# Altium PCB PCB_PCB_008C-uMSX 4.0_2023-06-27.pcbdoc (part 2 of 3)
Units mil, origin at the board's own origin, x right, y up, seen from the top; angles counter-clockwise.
Board outline 14478.11 x 5217.07 mil, 2 copper layers (Top Layer, Bottom Layer); 184 components, 339 nets, 1501 pads, 946 vias.
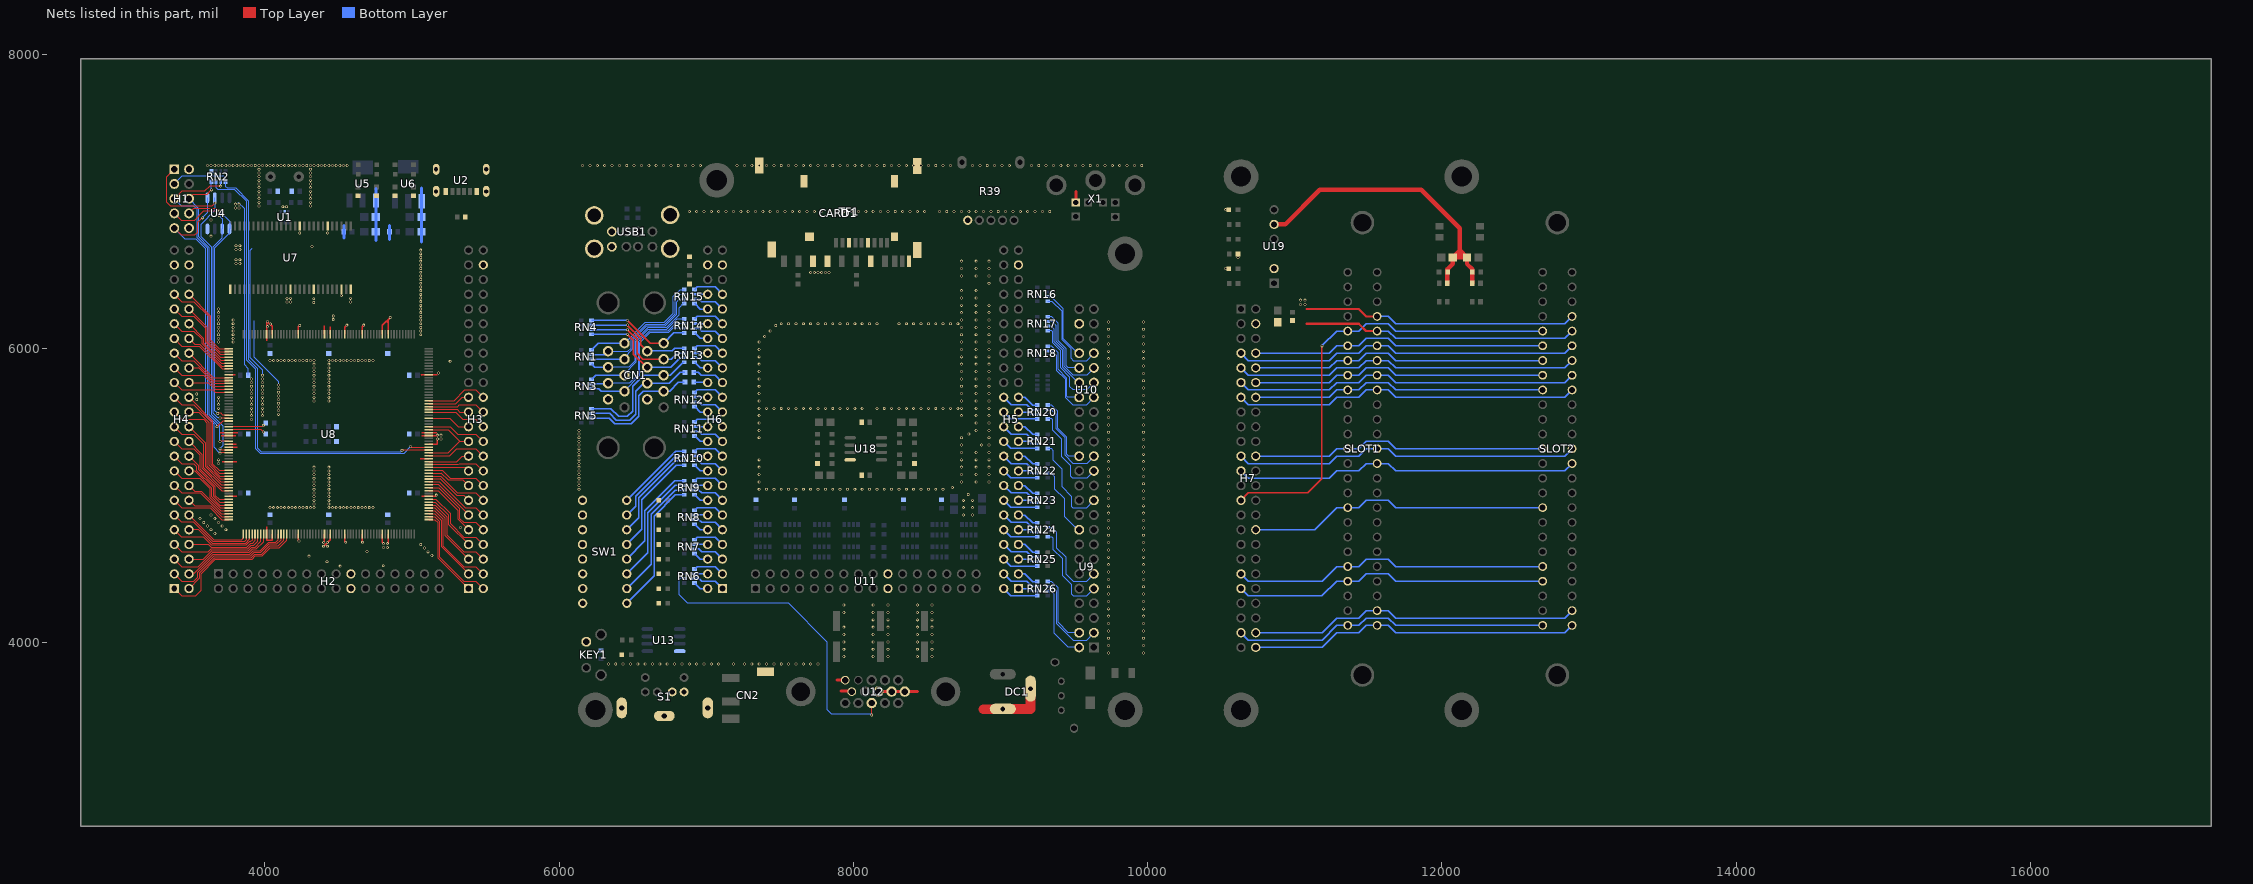
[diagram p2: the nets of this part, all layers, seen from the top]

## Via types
v1: diameter 20, hole 12, Top Layer to Bottom Layer, 944 vias
v2: diameter 24, hole 12, Top Layer to Bottom Layer, 2 vias

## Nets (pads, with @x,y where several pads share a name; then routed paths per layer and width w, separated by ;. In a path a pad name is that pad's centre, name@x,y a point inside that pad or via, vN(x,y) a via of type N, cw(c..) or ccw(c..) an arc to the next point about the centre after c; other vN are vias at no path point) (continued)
A12: H7.23 RN20.8 SLOT1.23 SLOT2.23 U10.1 | length 3008
  Bottom Layer w6: RN20.8@9320.43,5519.81 9347.24,5519.81 9354,5513.05 9354,5443.05 9415,5382.05 9415,5261.59 9476,5200.59 9476,5131.05 9490,5117.05 9585,5117.05 U10.1@9635,5167.05
  Bottom Layer w10: H7.23@10635,5167.05 10685,5117.05 11235,5117.05 11285,5167.05 11435,5167.05 11485.03,5217.08 SLOT1.23@11560,5217.08 11634.98,5217.08 11685.01,5167.05 12834.97,5167.05 SLOT2.23@12885,5217.08
A13: H7.22 RN20.5 SLOT1.26 SLOT2.26 U10.4 | length 2506.4
  Bottom Layer w6: RN20.5@9320.43,5614.29 9347.76,5614.29 9390,5572.05 9390,5457.96 9451,5396.96 9451,5279.08 9463.03,5267.05 U10.4@9535,5267.05
  Bottom Layer w10: H7.22@10735,5267.05 11235,5267.05 11285,5317.05 SLOT1.26@11359.97,5317.05 ; SLOT1.26@11360,5317.08 11435.02,5317.08 11484.99,5367.05 11635.01,5367.05 11684.98,5317.08 SLOT2.26@12685,5317.08
A14: H7.21 RN20.6 SLOT1.25 SLOT2.25 U10.3 | length 2966.7
  Bottom Layer w6: RN20.6@9320.43,5582.8 9345.91,5582.8 9378,5550.71 9378,5452.99 9439,5391.99 9439,5274.11 9496.06,5217.05 9585,5217.05 U10.3@9635,5267.05
  Bottom Layer w10: H7.21@10635,5267.05 10685,5217.05 11235,5217.05 11285,5267.05 11435,5267.05 11485.03,5317.08 SLOT1.25@11560,5317.08 11634.98,5317.08 11685.01,5267.05 12834.97,5267.05 SLOT2.25@12885,5317.08
A15: H7.32 RN22.7 SLOT1.18 SLOT2.18 U9.18 | length 2551.6
  Bottom Layer w6: RN22.7@9320.43,5151.3 9345.75,5151.3 9367,5130.05 9367,5047.02 9432,4982.02 9432,4859.9 9529.93,4761.97 U9.18@9535,4767.05
  Bottom Layer w10: H7.32@10735,4767.05 11136.97,4767.05 11287,4917.08 SLOT1.18@11360,4917.08 11435.03,4917.08 11485,4967.05 11635,4967.05 11684.97,4917.08 SLOT2.18@12685,4917.08
AS_CK: H1.1 U4.6 U8.36 | length 2462.8
  Top Layer w6: H1.1@3385,7217.05 3335,7167.05 3335,6992.05 3360,6967.05 3640,6967.05 v1@3655,6982.05 ; v1(3695,5317.05) 3703.27,5308.78 U8.36@3755.86,5308.78
  Bottom Layer w6: U4.6@3660,7022.66 v1(3660,6987.05) 3660,6937.05 3564,6841.05 3564,6761.99 3636,6689.99 3636,5553.02 3715,5474.02 3715,5337.05 v1(3695,5317.05)
AS_CS: H1.8 U4.1 U8.24 | length 1758.2
  Top Layer w6: H1.8@3485,6917.05 3515,6947.05 3675,6947.05 v1(3690,6932.05) ; v1(3680,5557.05) 3702.95,5557.05 3715,5545 U8.24@3755.86,5545
  Bottom Layer w6: v1(3680,5557.05) 3660,5577.05 3660,6685.08 3760,6785.08 U4.1@3760,6811.44 3760,6862.05 v1(3690,6932.05)
AS_DI: H1.7 U4.2 U8.25 | length 1862.8
  Top Layer w6: H1.7@3385,6917.05 3435,6867.05 3520,6867.05 3583,6930.05 3662,6930.05 v1(3690,6902.05) ; v1(3695,5527.05) 3696.73,5525.32 U8.25@3755.86,5525.32
  Bottom Layer w6: v1(3690,6902.05) 3710,6882.05 U4.2@3710,6811.44 3710,6752.05 3648,6690.05 3648,5557.99 3678.94,5527.05 v1(3695,5527.05)
AS_DO: H1.9 U4.5 U8.37 | length 2211.5
  Top Layer w6: H1.9@3385,6817.05 3435,6767.05 3520,6767.05 3540,6787.05 3540,6852.05 v1(3575,6887.05) ; v1(3695,5287.05) 3697.05,5289.1 U8.37@3755.86,5289.1
  Bottom Layer w6: H1.9@3385,6817.05 3460,6742.05 3533.03,6742.05 3600,6675.08 3600,5538.11 3655,5483.11 3655,5327.05 v1(3695,5287.05) ; v1(3575,6887.05) 3575,6887.66 3610,6922.66 U4.5@3610,7022.66
BDIR: H7.37 RN24.6 SLOT1.10 SLOT2.10 U9.11 | length 2814.1
  Bottom Layer w6: RN24.6@9320.43,4782.8 9349.25,4782.8 9380.03,4752.02 9380.03,4645.96 9444,4581.99 9444,4468.05 9495,4417.05 9585,4417.05 U9.11@9635,4467.05
  Bottom Layer w10: H7.37@10635,4467.05 10685,4417.05 11186.97,4417.05 11286.97,4517.05 11360,4517.05 11404.94,4517.05 ; SLOT1.10@11360,4517.08 11404.94,4517.08 11435.03,4517.08 11485,4567.05 11635,4567.05 11684.97,4517.08 SLOT2.10@12685,4517.08
C_CE: H1.6 RN2.4 U8.33 | length 2030.2
  Top Layer w6: H1.6@3485,7017.05 3515,7047.05 3607.5,7047.05 v1(3637.5,7077.05) ; v1(3695,5367.05) 3755.07,5367.05 U8.33@3755.86,5367.84
  Bottom Layer w6: H1.6@3485,7017.05 3552,6950.05 3552,6757.02 3624,6685.02 3624,5548.05 3695,5477.05 v1(3695,5367.05) ; v1(3637.5,7077.05) 3637.5,7131.35 RN2.4@3637.76,7131.61
C_CONF: H1.5 RN2.2 U8.26 | length 2195.7
  Top Layer w6: H1.5@3385,7017.05 3435,7067.05 3590,7067.05 3625,7102.05 v1(3700,7102.05) ; v1(3675,5467.05) 3713.58,5505.63 U8.26@3755.86,5505.63
  Bottom Layer w6: H1.5@3385,7017.05 3435,6967.05 3518.03,6967.05 3540,6945.08 3540,6752.05 3612,6680.05 3612,5543.08 3675,5480.08 v1(3675,5467.05) ; v1(3700,7102.05) 3700.75,7102.8 RN2.2@3700.75,7131.61
C_DONE: H1.3 RN2.1 U8.145 | length 3510.8
  Top Layer w6: v1(4932.5,5307.05) 4934.23,5308.78 U8.145@5114.14,5308.78
  Bottom Layer w6: H1.3@3385,7117.05 3436,7168.05 3721.55,7168.05 3732.24,7157.36 RN2.1@3732.24,7131.61 3732.24,7101.61 3743.8,7090.05 3802.29,7090.05 3888.5,7003.84 3888.5,5925.52 3950,5864.02 3950,5324.02 3976.97,5297.05 4922.5,5297.05 v1(4932.5,5307.05)
C_STAT: RN2.3 U8.146 | length 3201.4
  Top Layer w6: v1(4990,5332.05) 4993.58,5328.47 U8.146@5114.14,5328.47
  Bottom Layer w6: RN2.3@3669.25,7131.61 3669.25,7092.8 3684,7078.05 3797.32,7078.05 3876.5,6998.87 3876.5,5920.55 3938,5859.05 3938,5319.05 3972,5285.05 4943,5285.05 v1(4990,5332.05)
CLK21M: R9.2 U8.28 | length 238.6
  Top Layer w6: U8.28@3755.86,5466.26 3979.21,5466.26 v1(3990,5477.05)
CLOCK: H7.27 RN21.8 SLOT1.42 SLOT2.42 U9.21 | length 3750.4
  Top Layer w10: H7.27@10635,4967.05 10685,5017.05 11090,5017.05 11185,5112.05 v1(11185,6017.05)
  Bottom Layer w6: RN21.8@9320.43,5319.81 9344,5319.81 9355,5308.81 9355,5242.05 9415,5182.05 9415,5061.59 9482.03,4994.56 9482.03,4925.02 9490,4917.05 9585,4917.05 U9.21@9635,4967.05
  Bottom Layer w10: v1(11185,6017.05) 11285.02,6117.07 SLOT1.42@11360,6117.07 11435,6117.07 11484.98,6167.05 11635.02,6167.05 11685,6117.07 SLOT2.42@12685,6117.07
CS1: H7.48 RN26.7 SLOT1.1 SLOT2.1 U9.2 | length 2784.3
  Bottom Layer w6: RN26.7@9320.43,4351.3 9345.75,4351.3 9367,4330.05 9367,4062.02 9461.97,3967.05 U9.2@9535,3967.05
  Bottom Layer w10: H7.48@10735,3967.05 11186.97,3967.05 11286.97,4067.05 11434.99,4067.05 11485.02,4117.08 SLOT1.1@11560,4117.08 11634.97,4117.08 11685,4067.05 12834.97,4067.05 SLOT2.1@12885,4117.08
CS2: H7.45 RN26.6 SLOT1.2 SLOT2.2 U9.3 | length 2769.2
  Bottom Layer w6: RN26.6@9320.43,4382.8 9349.25,4382.8 9379,4353.05 9379,4133.05 9495,4017.05 9585,4017.05 U9.3@9635,4067.05
  Bottom Layer w10: H7.45@10635,4067.05 10685,4017.05 11186.97,4017.05 11287,4117.08 SLOT1.2@11360,4117.08 11435.02,4117.08 11484.99,4167.05 11635,4167.05 11684.97,4117.08 SLOT2.2@12685,4117.08
CS12: H7.46 RN26.5 SLOT1.3 SLOT2.3 U9.4 | length 2748.5
  Bottom Layer w6: RN26.5@9320.43,4414.29 9347.76,4414.29 9391,4371.05 9391,4138.02 9461.97,4067.05 U9.4@9535,4067.05
  Bottom Layer w10: H7.46@10735,4067.05 11186.97,4067.05 11286.97,4167.05 11435,4167.05 11485.03,4217.08 SLOT1.3@11560,4217.08 11634.97,4217.08 11685,4167.05 12834.97,4167.05 SLOT2.3@12885,4217.08
D0: H7.14 RN18.5 SLOT1.34 SLOT2.34 U10.12 | length 2509.9
  Bottom Layer w6: RN18.5@9320.43,6014.29 9347.76,6014.29 9391,5971.05 9391,5856.96 9451,5796.96 9451,5673.05 9457,5667.05 U10.12@9535,5667.05
  Bottom Layer w10: H7.14@10735,5667.05 11235,5667.05 11285,5717.05 11359.98,5717.05 11435.02,5717.07 11485,5767.05 11635,5767.05 11684.98,5717.07 SLOT2.34@12685,5717.07
D1: H7.13 RN18.6 SLOT1.33 SLOT2.33 U10.11 | length 2972.2
  Bottom Layer w6: RN18.6@9320.43,5982.8 9349.25,5982.8 9379,5953.05 9379,5851.99 9439,5791.99 9439,5667.99 9489.95,5617.05 9585,5617.05 U10.11@9635,5667.05
  Bottom Layer w10: H7.13@10635,5667.05 10685,5617.05 11235,5617.05 11285,5667.05 11435,5667.05 11485.02,5717.07 SLOT1.33@11560,5717.07 11634.98,5717.07 11685,5667.05 12834.98,5667.05 SLOT2.33@12885,5717.07
D2: H7.12 RN17.7 SLOT1.36 SLOT2.36 U10.14 | length 2504.8
  Bottom Layer w6: RN17.7@9320.43,6151.3 9345.75,6151.3 9367,6130.05 9367,6043.08 9422,5988.08 9422,5872.02 9526.97,5767.05 U10.14@9535,5767.05
  Bottom Layer w10: H7.12@10735,5767.05 11235,5767.05 11285,5817.05 11359.98,5817.05 11435.02,5817.07 11485,5867.05 11635,5867.05 11684.98,5817.07 SLOT2.36@12685,5817.07
D3: H7.11 RN17.8 SLOT1.35 SLOT2.35 U10.13 | length 3005.1
  Bottom Layer w6: RN17.8@9320.43,6119.81 9347.24,6119.81 9355,6112.05 9355,6037.05 9410,5982.05 9410,5867.05 9472,5805.05 9472,5740.05 9495,5717.05 9585,5717.05 U10.13@9635,5767.05
  Bottom Layer w10: H7.11@10635,5767.05 10685,5717.05 11235,5717.05 11285,5767.05 11435,5767.05 11485.02,5817.07 SLOT1.35@11560,5817.07 11634.98,5817.07 11685,5767.05 12834.98,5767.05 SLOT2.35@12885,5817.07
D4: H7.10 RN17.5 SLOT1.38 SLOT2.38 U10.16 | length 2507.6
  Bottom Layer w6: RN17.5@9320.43,6214.29 9347.76,6214.29 9391,6171.05 9391,6053.02 9446,5998.02 9446,5881.96 9460.91,5867.05 U10.16@9535,5867.05
  Bottom Layer w10: H7.10@10735,5867.05 11235,5867.05 11285.02,5917.07 SLOT1.38@11360,5917.07 11435.02,5917.07 11485,5967.05 11635,5967.05 11684.98,5917.07 SLOT2.38@12685,5917.07
D5: H7.9 RN17.6 SLOT1.37 SLOT2.37 U10.15 | length 2969.8
  Bottom Layer w6: RN17.6@9320.43,6182.8 9349.25,6182.8 9379,6153.05 9379,6048.05 9434,5993.05 9434,5876.99 9493.94,5817.05 9585,5817.05 U10.15@9635,5867.05
  Bottom Layer w10: H7.9@10635,5867.05 10685,5817.05 11235,5817.05 11285,5867.05 11435,5867.05 11485.02,5917.07 SLOT1.37@11560,5917.07 11634.98,5917.07 11685,5867.05 12834.98,5867.05 SLOT2.37@12885,5917.07
D6: H7.8 RN16.7 SLOT1.40 SLOT2.40 U10.18 | length 2504.7
  Bottom Layer w6: RN16.7@9320.43,6351.3 9345.23,6351.3 9427,6269.53 9427,6066.56 9526.51,5967.05 U10.18@9535,5967.05
  Bottom Layer w10: H7.8@10735,5967.05 11235,5967.05 11285.02,6017.07 SLOT1.40@11360,6017.07 11435.02,6017.07 11485,6067.05 11635,6067.05 11684.98,6017.07 SLOT2.40@12685,6017.07
D7: H7.7 RN16.8 SLOT1.39 SLOT2.39 U10.17 | length 3006.5
  Bottom Layer w6: RN16.8@9320.43,6319.81 9349.75,6319.81 9415,6254.56 9415,6061.59 9477,5999.59 9477,5935.05 9495,5917.05 9585,5917.05 U10.17@9635,5967.05
  Bottom Layer w10: H7.7@10635,5967.05 10685,5917.05 11235.02,5917.05 11285.02,5967.05 11435,5967.05 11485.02,6017.07 SLOT1.39@11560,6017.07 11634.98,6017.07 11685,5967.05 12834.98,5967.05 SLOT2.39@12885,6017.07
DIP0: RN10.8 SW1.16 | length 527.7
  Bottom Layer w10: SW1.16@6459.5,4966.95 6791.84,5299.29 RN10.8@6849.56,5299.29
DIP1: RN10.7 SW1.15 | length 595.6
  Bottom Layer w10: SW1.15@6459.5,4866.95 6520,4927.45 6520,4994.82 6792.98,5267.8 RN10.7@6849.56,5267.8
DIP2: RN10.6 SW1.14 | length 663.4
  Bottom Layer w10: SW1.14@6459.5,4766.95 6541,4848.45 6541,4983.19 6794.1,5236.3 RN10.6@6849.56,5236.3
DIP3: RN10.5 SW1.13 | length 731.3
  Bottom Layer w10: SW1.13@6459.5,4666.95 6562,4769.45 6562,4971.57 6795.24,5204.81 RN10.5@6849.56,5204.81
DIP4: RN9.8 SW1.12 | length 729.8
  Bottom Layer w10: SW1.12@6459.7,4567.45 6583,4690.75 6583,4894.94 6787.35,5099.29 RN9.8@6849.56,5099.29
DIP5: RN9.7 SW1.11 | length 797.6
  Bottom Layer w10: SW1.11@6460.5,4467.15 6604,4610.65 6604,4883.31 6788.49,5067.8 RN9.7@6849.56,5067.8
DIP6: RN9.6 SW1.10 | length 865.4
  Bottom Layer w10: SW1.10@6460.5,4367.15 6625,4531.65 6625,4871.68 6789.61,5036.3 RN9.6@6849.56,5036.3
DIP7: RN9.5 SW1.9 | length 933.3
  Bottom Layer w10: SW1.9@6460.5,4267.15 6646,4452.65 6646,4860.06 6790.75,5004.81 RN9.5@6849.56,5004.81
EXTCLK: R10.2 U8.29 | length 240.2
  Top Layer w6: U8.29@3755.86,5446.58 3975.47,5446.58 v1(3990,5432.05)
GND: 5V.1@10551.5,6541.65 +12V.1 C1.1 C2.1 C3.1 C4.1 C5.1 C6.1 C7.1 C8.1 C9.1 C10.1 C11.1 C12.1 C13.1 C14.1 C15.1 C16.1 C17.1 C18.1 C19.1 C20.1 C21.1 C22.2 C23.2 C24.2 C32.1 C33.2 C38.1 C39.1 C40.1 C41.2 C42.1 C43.1 CARD1.2 CARD1.3 CARD1.6 CARD1.11 CARD1.12 CARD1.13 CARD1.14 CARD1.15 CN1.9 CN1.18 CN2.1 DC1.2 DC1.3 H1.2 H1.10 H2.19 H2.20 H3.46 H4.45 H4.46 H5.45 H6.45 H6.46 H7.4 KEY1.1 LED5.1 LED6.1 LED7.1 LED8.1 LED9.1 LED10.1 LED11.1 LED12.1 LED13.1 R5.2 R6.2 R7.2 R8.2 R22.1 R23.1 R24.2 R25.2 R26.2 R27.2 R28.2 R32.2 R33.2 R39.1 R43.1 R45.1 R46.1 RN2.5 S1.2 S1.4 S1.7 S1.8 S1.9 SLOT1.41 SLOT1.43 SLOT2.41 SLOT2.43 SW1.1 SW1.2 SW1.3 SW1.4 SW1.5 SW1.6 SW1.7 SW1.8 TF1.3 TF1.6 TF1.10 TF1.11 TF1.12 TF1.13 U1.2 U2.7 U2.A12 U2.B12 U4.4 U5.1 U6.1 U7.6 U7.12 U7.28 U7.41 U7.46 U7.52 U7.54 U8.10 U8.30 U8.31 U8.34 U8.35 U8.40 U8.52 U8.69 U8.71 U8.80 U8.89 U8.91 U8.96 U8.102 U8.109 U8.111 U8.129 U8.142 U8.147 U8.150 U8.151 U8.171 U8.190 U8.192 U8.199 U8.205 U8.210 U8.212 U8.221 U8.230 U8.232 U10.22 U11.19 U11.20 U12.5 U12.6 U12.7 U12.8 U12.10 U13.4 U18.4 U19.2 U19.5 USB1.4 USB1.8 USB1.9 X1.3 | length 12989.5
  Top Layer w10: 3697.5,5427.05 3755.7,5427.05 U8.30@3755.86,5426.89 3815,5426.89 ; 3702.5,5407.05 3755.7,5407.05 U8.31@3755.86,5407.21 3802.5,5407.21 ; 3710,5229.55 3755.38,5229.55 U8.40@3755.86,5230.04 3809.51,5230.04 3810,5229.55 ; U8.52@3755.86,4993.82 3810,4993.82 ; U8.35@3755.86,5328.47 3812.5,5328.47 ; U8.34@3755.86,5348.15 3807.5,5348.15 ; U8.10@3755.86,5820.59 3800,5820.59 ; 4011.76,4787.05 U8.69@4011.76,4737.92 4011.76,4696.05 4051.14,4696.05 U8.71@4051.14,4737.92 ; 4011.78,6052.05 U8.232@4011.78,6096.18 4011.78,6176.32 v1(4017.5,6182.05) 4051.14,6148.4 U8.230@4051.14,6096.18 ; U8.80@4228.31,4737.92 4228.31,4693.74 v1(4232.5,4689.55) ; U8.221@4228.31,6096.18 4228.31,6145.35 v1(4237.5,6154.55) ; v1(4400,4654.55) v1(4425,4679.55) 4444.84,4699.38 U8.91@4444.84,4737.92 ; v1(4400,4679.55) 4405.47,4685.01 U8.89@4405.47,4737.92 ; U8.212@4405.48,6096.18 4405.48,6154.55 ; U8.210@4444.85,6096.18 4444.85,6147.05 ; U8.96@4543.27,4737.92 4543.27,4688.78 v1(4550,4682.05) ; U8.205@4543.27,6096.18 4543.27,6142.81 v1(4557.5,6157.05) ; U8.102@4661.38,4737.92 4661.38,4685.67 v1(4665,4682.05) ; U8.199@4661.38,6096.18 4661.38,6145.92 v1(4672.5,6157.05) ; U8.109@4799.16,4737.92 4799.16,4680.38 v1(4807.5,4672.05) ; U8.192@4799.16,6096.18 4799.16,6156.21 4822.22,6179.27 ; v1(4832.5,4672.05) 4838.53,4678.08 U8.111@4838.53,4737.92 ; U8.190@4838.53,6096.18 4838.53,6172.83 ; v1(4852.5,6209.55) 4838.53,6195.58 ; 5055,5249.73 U8.142@5114.14,5249.73 ; 5062.5,5817.05 5066.04,5820.59 U8.171@5114.14,5820.59 5172.5,5820.59 ; 5065,5407.05 5113.98,5407.05 U8.150@5114.14,5407.21 5170.16,5407.21 v1(5172.5,5409.55) ; 5067.5,4994.55 5113.4,4994.55 U8.129@5114.14,4993.82 5156.77,4993.82 v1(5165,5002.05) ; 5067.5,5427.05 5113.98,5427.05 U8.151@5114.14,5426.89 5170,5426.89 ; U8.147@5114.14,5348.15 5172.5,5348.15 v1(5172.5,5384.55) ; 4822.22,6179.27 4832.1,6179.27 4838.53,6172.83 ; 4822.22,6179.27 4838.53,6195.58 ; 4838.53,6172.83 4838.53,6195.58
  Top Layer w15: 11080,6167.05 11435,6167.05 11484.98,6117.07 SLOT1.41@11560,6117.07 ; 11080,6267.05 11435,6267.05 11484.98,6217.07 SLOT1.43@11560,6217.07
  Top Layer w20: 7887.5,3744.55 7943.8,3744.55 U12.5@7944.25,3745 ; 7915,3669.55 7986.83,3669.55 U12.10@7989.33,3667.05 ; U12.8@8169.65,3667.05 U12.7@8259.8,3667.05 U12.6@8349.96,3667.05 8435,3667.05 ; X1.3@9512.01,6991.05 9512.01,7067.05
  Top Layer w30: U19.5@10860,6842.05 10935,6842.05 11170,7077.05 11860,7077.05 12121.87,6815.18 12121.87,6665.81 ; C43.1@12037.55,6442.05 12037.56,6536.66 12074.37,6573.47 C41.2@12074.37,6617.05 ; C42.1@12207.45,6442.05 12207.44,6536.66 12170.63,6573.47 C40.1@12170.63,6617.05 ; C41.2@12074.37,6617.05 12121.87,6617.05 ; C41.2@12074.37,6617.05 12121.87,6664.55 ; 12121.87,6617.05 C40.1@12170.63,6617.05 ; 12121.87,6617.05 12121.87,6664.55 ; 12121.87,6664.55 12121.87,6665.81 ; 12121.87,6665.81 C40.1@12170.63,6617.05
  Top Layer w66.93: 8885,3547.05 9013.62,3547.05 DC1.2@9015.51,3548.94 9204.49,3548.94 DC1.3@9204.49,3686.73
  Bottom Layer w6: 3820,6989.55 3862.5,6947.05 3862.5,5887.05 3887.56,5861.99 C21.1@3887.55,5817.05 ; 3915,6679.55 3900.5,6665.05 3900.5,5934.58 3985,5850.08 v1(3985,5817.05) ; 3926.5,6186.05 3926.5,5942.52 4092.5,5776.52 v1@4092.5,5747.05
  Bottom Layer w10: SLOT1.41@11560,6117.07 11634.98,6117.07 11685,6067.05 12834.98,6067.05 SLOT2.41@12885,6117.07 ; SLOT1.43@11560,6217.07 11634.98,6217.07 11685,6167.05 12834.98,6167.05 SLOT2.43@12885,6217.07
  Bottom Layer w20: 4537.44,6749.55 C17.1@4537.45,6792.05 4537.44,6834.55 ; 4755.55,6732.05 U5.1@4755.55,7004.55 4755.55,7087.05 ; 4847.5,6739.55 4847.5,6792.05 4847.5,6834.55 ; 5065.55,6722.05 U6.1@5065.55,7000.12 5065.55,7089.55
  other v1: 6335,3854.55 6385,3854.55 6435,3854.55 6485,3854.55 6535,3854.55 6585,3854.55 6635,3854.55 6685,3854.55 6735,3854.55 6785,3854.55 6835,3854.55 6885,3854.55 6935,3854.55 6985,3854.55 7035,3854.55 7085,3854.55 7185,3854.55 7260,3854.55 7310,3854.55 7360,3854.55 7410,3854.55 7460,3854.55 7510,3854.55 7560,3854.55 7610,3854.55 7660,3854.55 7710,3854.55 7760,3854.55 7935,3904.55 8135,3904.55 8235,3904.55 8435,3904.55 8535,3904.55 9735,3929.55 9972.5,3929.55 7935,3954.55 8135,3954.55 8235,3954.55 8435,3954.55 8535,3954.55 9735,3979.55 9972.5,3979.55 7935,4004.55 8135,4004.55 8235,4004.55 8435,4004.55 8535,4004.55 9735,4029.55 9972.5,4029.55 7935,4054.55 8135,4054.55 8235,4054.55 8435,4054.55 8535,4054.55 9735,4079.55 9972.5,4079.55 7935,4104.55 8135,4104.55 8235,4104.55 8435,4104.55 8535,4104.55 9735,4129.55 9972.5,4129.55 8135,4154.55 8235,4154.55 8435,4154.55 8535,4154.55 9735,4179.55 9972.5,4179.55 7935,4204.55 8135,4204.55 8235,4204.55 8435,4204.55 8535,4204.55 9735,4229.55 9972.5,4229.55 7935,4254.55 8135,4254.55 8235,4254.55 8435,4254.55 8535,4254.55 9735,4279.55 9972.5,4279.55 9735,4329.55 9972.5,4329.55 9735,4379.55 9972.5,4379.55 9735,4429.55 9972.5,4429.55 9735,4479.55 9972.5,4479.55 4512.5,4519.55 4805,4522.05 9735,4529.55 9972.5,4529.55 4422.5,4549.55 9735,4579.55 9972.5,4579.55 4300,4587.05 5135,4592.05 5110,4617.05 4695,4619.55 9735,4629.55 9972.5,4629.55 5085,4642.05 4807.5,4647.05 4832.5,4647.05 4425,4654.55 5060,4667.05 9735,4679.55 9972.5,4679.55 9735,4729.55 9972.5,4729.55 3660,4742.05 3635,4767.05 3735,4767.05 9735,4779.55 9972.5,4779.55 5330,4782.05 3610,4792.05 3710,4792.05 3585,4817.05 3685,4817.05 9735,4829.55 9972.5,4829.55 3560,4842.05 3660,4842.05 3635,4867.05 8747.5,4867.05 8810,4867.05 9735,4879.55 9972.5,4879.55 4035,4917.05 4060,4917.05 4085,4917.05 4110,4917.05 4135,4917.05 4160,4917.05 4185,4917.05 4210,4917.05 4235,4917.05 4260,4917.05 4285,4917.05 4310,4917.05 4335,4917.05 4435,4917.05 4460,4917.05 4485,4917.05 4510,4917.05 4535,4917.05 4560,4917.05 4585,4917.05 4610,4917.05 4635,4917.05 4660,4917.05 4685,4917.05 4710,4917.05 4735,4917.05 8747.5,4917.05 8810,4917.05 9735,4929.55 9972.5,4929.55 4335,4942.05 4435,4942.05 4335,4967.05 4435,4967.05 8747.5,4967.05 8810,4967.05 9735,4979.55 9972.5,4979.55 4335,4992.05 4435,4992.05 8781,5006.05 4335,5017.05 4435,5017.05 9735,5029.55 9972.5,5029.55 4335,5042.05 4435,5042.05 6135,5042.05 7360,5042.05 7410,5042.05 7460,5042.05 7510,5042.05 7560,5042.05 7610,5042.05 7660,5042.05 7710,5042.05 7760,5042.05 7810,5042.05 7860,5042.05 7910,5042.05 7960,5042.05 8010,5042.05 8060,5042.05 8110,5042.05 8160,5042.05 8210,5042.05 8260,5042.05 8310,5042.05 8360,5042.05 8410,5042.05 8460,5042.05 8510,5042.05 8560,5042.05 8610,5042.05 8672.5,5054.55 4335,5067.05 4435,5067.05 6135,5067.05 9735,5079.55 9972.5,5079.55 4335,5092.05 4435,5092.05 6135,5092.05 7360,5092.05 8735,5092.05 8835,5092.05 8922.5,5092.05 4335,5117.05 4435,5117.05 6135,5117.05 9735,5129.55 9972.5,5129.55 4335,5142.05 4435,5142.05 6135,5142.05 7360,5142.05 8735,5142.05 8835,5142.05 8922.5,5142.05 4335,5167.05 4435,5167.05 6135,5167.05 9735,5179.55 9972.5,5179.55 4335,5192.05 4435,5192.05 6135,5192.05 7360,5192.05 8735,5192.05 8835,5192.05 8922.5,5192.05 3685,5217.05 6135,5217.05 9735,5229.55 9972.5,5229.55 3685,5242.05 6135,5242.05 7360,5242.05 8735,5242.05 8835,5242.05 8922.5,5242.05 6135,5267.05 9735,5279.55 9972.5,5279.55 6135,5292.05 8735,5292.05 8835,5292.05 8922.5,5292.05 6135,5317.05 9735,5329.55 9972.5,5329.55 6135,5342.05 8735,5342.05 8872.5,5342.05 8922.5,5342.05 6135,5367.05 9735,5379.55 9972.5,5379.55 5197.5,5384.55 6135,5392.05 7360,5392.05 8735,5392.05 8922.5,5392.05 5197.5,5409.55 6135,5417.05 8785,5417.05 9735,5429.55 9972.5,5429.55 6135,5442.05 7360,5442.05 8835,5442.05 8922.5,5442.05 9735,5479.55 9972.5,5479.55 7360,5492.05 8835,5492.05 8922.5,5492.05 3910,5517.05 9735,5529.55 9972.5,5529.55 3910,5542.05 3985,5542.05 7360,5542.05 8735,5542.05 8835,5542.05 8922.5,5542.05 4092.5,5551.52 3910,5567.05 3985,5567.05 4092.5,5576.52 9735,5579.55 9972.5,5579.55 3685,5592.05 3910,5592.05 3985,5592.05 7360,5592.05 7410,5592.05 7460,5592.05 7510,5592.05 7560,5592.05 7610,5592.05 7660,5592.05 7710,5592.05 7760,5592.05 7810,5592.05 7860,5592.05 7910,5592.05 7960,5592.05 8010,5592.05 8060,5592.05 8160,5592.05 8210,5592.05 8260,5592.05 8310,5592.05 8360,5592.05 8410,5592.05 8460,5592.05 8510,5592.05 8560,5592.05 8610,5592.05 8660,5592.05 8710,5592.05 8735,5592.05 8835,5592.05 8922.5,5592.05 4092.5,5601.52 3685,5617.05 3910,5617.05 3985,5617.05 4092.5,5626.52 9735,5629.55 9972.5,5629.55 3685,5642.05 3910,5642.05 3985,5642.05 4335,5642.05 4435,5642.05 7360,5642.05 8735,5642.05 8835,5642.05 8922.5,5642.05 3537.5,5652.29 4092.5,5651.52 3685,5667.05 3910,5667.05 3985,5667.05 4335,5667.05 4435,5667.05 4092.5,5676.52 9735,5679.55 9972.5,5679.55 3537.5,5689.55 3910,5692.05 3985,5692.05 4335,5692.05 4435,5692.05 7360,5692.05 8735,5692.05 8835,5692.05 8922.5,5692.05 4092.5,5701.52 3910,5717.05 3985,5717.05 4335,5717.05 4435,5717.05 4092.5,5726.52 9735,5729.55 9972.5,5729.55 3910,5742.05 3985,5742.05 4335,5742.05 4435,5742.05 7360,5742.05 8735,5742.05 8835,5742.05 8922.5,5742.05 4092.5,5751.52 3910,5767.05 3985,5767.05 4335,5767.05 4435,5767.05 9735,5779.55 9972.5,5779.55 3910,5792.05 3985,5792.05 4335,5792.05 4435,5792.05 7360,5792.05 8735,5792.05 8835,5792.05 8922.5,5792.05 4335,5817.05 4435,5817.05 9735,5829.55 9972.5,5829.55 5180,5832.05 4335,5842.05 4435,5842.05 7360,5842.05 8735,5842.05 8835,5842.05 8922.5,5842.05 4335,5867.05 4435,5867.05 9735,5879.55 9972.5,5879.55 4335,5892.05 4435,5892.05 7360,5892.05 8735,5892.05 8835,5892.05 8922.5,5892.05 5260,5912.05 4035,5917.05 4060,5917.05 4085,5917.05 4110,5917.05 4135,5917.05 4160,5917.05 4185,5917.05 4210,5917.05 4235,5917.05 4260,5917.05 4285,5917.05 4310,5917.05 4335,5917.05 4435,5917.05 4460,5917.05 4485,5917.05 4510,5917.05 4535,5917.05 4560,5917.05 4585,5917.05 4610,5917.05 4635,5917.05 4660,5917.05 4685,5917.05 4710,5917.05 4735,5917.05 9735,5929.55 9972.5,5929.55 7360,5942.05 8735,5942.05 8835,5942.05 8922.5,5942.05 9735,5979.55 9972.5,5979.55 7360,5992.05 8735,5992.05 8835,5992.05 8922.5,5992.05 9735,6029.55 9972.5,6029.55 3685,6042.05 3785,6042.05 7360,6042.05 8735,6042.05 8835,6042.05 8922.5,6042.05 3685,6067.05 3785,6067.05 7397.5,6079.55 9735,6079.55 9972.5,6079.55 3685,6092.05 3785,6092.05 5060,6092.05 8735,6092.05 8835,6092.05 8922.5,6092.05 3685,6117.05 3785,6117.05 5060,6117.05 7435,6117.05 9735,6129.55 9972.5,6129.55 3685,6142.05 3785,6142.05 5060,6142.05 8735,6142.05 8835,6142.05 8922.5,6142.05 4017.5,6147.05 7472.5,6154.55 4037.5,6164.55 3685,6167.05 3785,6167.05 5060,6167.05 7510,6167.05 7560,6167.05 7610,6167.05 7660,6167.05 7710,6167.05 7760,6167.05 7810,6167.05 7860,6167.05 7910,6167.05 7960,6167.05 8010,6167.05 8060,6167.05 8110,6167.05 8160,6167.05 8310,6167.05 8360,6167.05 8410,6167.05 8460,6167.05 8510,6167.05 8560,6167.05 8610,6167.05 8660,6167.05 8710,6167.05 9735,6179.55 9972.5,6179.55 3685,6192.05 3785,6192.05 5060,6192.05 8735,6192.05 8835,6192.05 8922.5,6192.05 4465,6194.55 3685,6217.05 5060,6217.05 4465,6219.55 3685,6242.05 5060,6242.05 8735,6242.05 8835,6242.05 8922.5,6242.05 3685,6267.05 5060,6267.05 5060,6292.05 8735,6292.05 8835,6292.05 8922.5,6292.05 11040,6297.05 11070,6297.05 4332.5,6312.05 4150,6314.55 4175,6314.55 4582.5,6314.55 5060,6317.05 11040,6327.05 11070,6327.05 4332.5,6337.05 4150,6339.55 4175,6339.55 4582.5,6339.55 5060,6342.05 8735,6342.05 8835,6342.05 4520,6359.55 5060,6367.05 5060,6392.05 8735,6392.05 8835,6392.05 5060,6417.05 5060,6442.05 8922.5,6442.05 5060,6467.05 5060,6492.05 8735,6492.05 8835,6492.05 8922.5,6492.05 7710,6514.55 7735,6514.55 7760,6514.55 7785,6514.55 7810,6514.55 7835,6514.55 5060,6517.05 5060,6542.05 8735,6542.05 8835,6542.05 8922.5,6542.05 10530,6542.05 5060,6567.05 3805,6577.05 3830,6577.05 5060,6592.05 8735,6592.05 8835,6592.05 8922.5,6592.05 3805,6602.05 3830,6602.05 5060,6617.05 10615,6617.05 5060,6642.05 5060,6667.05 3805,6672.05 3830,6672.05 4320,6692.05 3805,6697.05 3830,6697.05 3635,6762.05 4237.5,6784.55 4427.5,6784.55 3635,6872.05 6885,6929.55 6935,6929.55 6985,6929.55 7035,6929.55 7085,6929.55 7135,6929.55 7185,6929.55 7235,6929.55 7285,6929.55 7335,6929.55 7385,6929.55 7435,6929.55 7485,6929.55 7535,6929.55 7585,6929.55 7635,6929.55 7685,6929.55 7735,6929.55 7785,6929.55 7835,6929.55 7885,6929.55 7935,6929.55 7985,6929.55 8035,6929.55 8085,6929.55 8135,6929.55 8185,6929.55 8235,6929.55 8285,6929.55 8335,6929.55 8385,6929.55 8435,6929.55 8485,6929.55 8585,6929.55 8635,6929.55 8685,6929.55 8735,6929.55 8785,6929.55 8835,6929.55 8885,6929.55 8935,6929.55 8985,6929.55 9035,6929.55 9085,6929.55 9135,6929.55 9185,6929.55 9235,6929.55 9285,6929.55 9335,6929.55 10530,6942.05 3800,6954.55 3825,6954.55 4122.5,6962.05 4147.5,6962.05 3960,6967.05 4310,6967.05 3800,6979.55 3825,6979.55 3960,6992.05 4310,6992.05 3960,7017.05 4310,7017.05 3960,7042.05 4310,7042.05 3960,7067.05 4310,7067.05 3960,7092.05 4310,7092.05 3960,7117.05 4310,7117.05 3960,7142.05 4310,7142.05 3960,7167.05 4310,7167.05 3960,7192.05 4310,7192.05 3960,7217.05 4310,7217.05 3610,7242.05 3635,7242.05 3660,7242.05 3685,7242.05 3710,7242.05 3735,7242.05 3760,7242.05 3785,7242.05 3810,7242.05 3835,7242.05 3860,7242.05 3885,7242.05 3910,7242.05 3935,7242.05 3960,7242.05 3985,7242.05 4010,7242.05 4035,7242.05 4060,7242.05 4085,7242.05 4110,7242.05 4135,7242.05 4160,7242.05 4185,7242.05 4210,7242.05 4235,7242.05 4260,7242.05 4285,7242.05 4310,7242.05 4335,7242.05 4360,7242.05 4385,7242.05 4410,7242.05 4435,7242.05 4460,7242.05 4485,7242.05 4510,7242.05 4535,7242.05 4560,7242.05 6160,7242.05 6210,7242.05 6260,7242.05 6310,7242.05 6360,7242.05 6410,7242.05 6460,7242.05 6510,7242.05 6560,7242.05 6610,7242.05 6660,7242.05 6710,7242.05 6760,7242.05 6810,7242.05 6860,7242.05 6910,7242.05 6960,7242.05 7210,7242.05 7260,7242.05 7310,7242.05 7360,7242.05 7410,7242.05 7460,7242.05 7510,7242.05 7560,7242.05 7610,7242.05 7660,7242.05 7710,7242.05 7760,7242.05 7810,7242.05 7860,7242.05 7910,7242.05 7960,7242.05 8010,7242.05 8060,7242.05 8110,7242.05 8160,7242.05 8210,7242.05 8260,7242.05 8310,7242.05 8360,7242.05 8410,7242.05 8460,7242.05 8510,7242.05 8560,7242.05 8610,7242.05 8660,7242.05 8810,7242.05 8860,7242.05 8910,7242.05 8960,7242.05 9010,7242.05 9060,7242.05 9210,7242.05 9260,7242.05 9310,7242.05 9360,7242.05 9410,7242.05 9460,7242.05 9510,7242.05 9560,7242.05 9610,7242.05 9660,7242.05 9710,7242.05 9760,7242.05 9810,7242.05 9860,7242.05 9910,7242.05 9960,7242.05
HSYNC: RN6.6 U12.13 | length 2140.6
  Top Layer w6: U12.13@8124.57,3589.1 8125,3588.67 v1(8125,3507.05)
  Bottom Layer w6: RN6.6@6849.56,4436.3 6824.25,4436.3 6814,4426.05 6814,4326.99 6870.94,4270.05 7555.94,4270.05 7819,4006.99 7819,3548.05 7850,3517.05 8115,3517.05 v1(8125,3507.05)
INT: H7.39 RN24.8 SLOT1.8 SLOT2.8 U9.9 | length 2849.9
  Bottom Layer w6: RN24.8@9320.43,4719.81 9347.24,4719.81 9356.03,4711.02 9356.03,4636.02 9420,4572.05 9420,4456.59 9481,4395.59 9481,4331.05 9495,4317.05 9585,4317.05 U9.9@9635,4367.05
  Bottom Layer w10: H7.39@10635,4367.05 10685,4317.05 11185,4317.05 11285,4417.05 11360,4417.05 11404.94,4417.05 ; SLOT1.8@11360,4417.08 11404.94,4417.08 11435.03,4417.08 11485,4467.05 11635,4467.05 11684.97,4417.08 SLOT2.8@12685,4417.08
IO0: CN1.1 RN1.5 RN15.8 | length 865.3
  Bottom Layer w6: CN1.1@6444.84,6035.16 6586.73,6177.05 6713.18,6177.05 6775.92,6239.79 6775.92,6352.97 6822.24,6399.29 RN15.8@6849.56,6399.29
  Bottom Layer w10: RN1.5@6220.44,5989.29 6266.31,6035.16 CN1.1@6444.84,6035.16
IO1: CN1.6 RN1.6 RN15.7 | length 893.4
  Bottom Layer w6: CN1.6@6333.03,5980.63 6468.32,5980.63 6489.74,6002.05 6489.74,6063.08 6591.7,6165.05 6718.15,6165.05 6787.92,6234.82 6787.92,6334.97 6820.75,6367.8 RN15.7@6849.56,6367.8
  Bottom Layer w10: RN1.6@6220.44,5957.8 6310.2,5957.8 CN1.6@6333.03,5980.63
IO2: CN1.2 RN1.7 RN15.6 | length 894.8
  Bottom Layer w6: CN1.2@6444.85,5926.1 6444.84,5940.18 6501.74,5997.08 6501.74,6058.11 6596.67,6153.05 6723.12,6153.05 6799.92,6229.85 6799.92,6316.97 6820,6337.05 6848.81,6337.05 RN15.6@6849.56,6336.3
  Bottom Layer w10: RN1.7@6220.44,5926.3 6444.64,5926.3 CN1.2@6444.85,5926.1
IO3: CN1.7 RN1.8 RN15.5 | length 928
  Bottom Layer w6: CN1.7@6333.03,5871.58 6472.4,5871.58 6513.74,5912.92 6513.74,6053.14 6601.64,6141.05 6728.09,6141.05 6811.92,6224.88 6811.92,6272.16 6844.56,6304.81 RN15.5@6849.56,6304.81
  Bottom Layer w10: RN1.8@6220.44,5894.81 6243.66,5871.58 CN1.7@6333.03,5871.58
IO4: CN1.3 RN3.5 RN14.8 | length 887
  Bottom Layer w6: CN1.3@6444.84,5817.05 6444.84,5827.05 6525.74,5907.94 6525.74,6048.17 6606.62,6129.05 6733.06,6129.05 6803.3,6199.29 RN14.8@6849.56,6199.29
  Bottom Layer w10: RN3.5@6220.44,5789.29 6248.19,5817.05 CN1.3@6444.84,5817.05
IO5: CN1.8 RN3.6 RN14.7 | length 928
  Bottom Layer w6: CN1.8@6333.03,5762.52 6477.4,5762.52 6537.74,5822.86 6537.74,6043.2 6611.59,6117.05 6738.03,6117.05 6788.78,6167.8 RN14.7@6849.56,6167.8
  Bottom Layer w10: RN3.6@6220.44,5757.8 6328.31,5757.8 CN1.8@6333.03,5762.52
IO6: CN1.4 RN3.7 RN14.6 | length 946.1
  Bottom Layer w6: CN1.4@6444.85,5707.99 6444.84,5712.99 6549.74,5817.89 6549.74,6038.23 6616.56,6105.05 6743,6105.05 6774.25,6136.3 RN14.6@6849.56,6136.3
  Bottom Layer w10: RN3.7@6220.44,5726.3 6270,5726.3 6288.31,5707.99 CN1.4@6444.85,5707.99
IO7: CN1.10 RN4.1 RN14.5 | length 721.8
  Top Layer w10: v1(6465,6189.29) 6619.13,6035.16 CN1.10@6710.98,6035.16
  Bottom Layer w10: RN4.1@6220.44,6189.29 v1(6465,6189.29) ; CN1.10@6710.98,6035.16 6780.63,6104.81 RN14.5@6849.56,6104.81
IO8: CN1.15 RN4.2 RN13.8 | length 735.4
  Top Layer w10: v1(6465,6157.8) 6554.17,6068.63 6554.17,6025.63 CN1.15@6599.17,5980.63
  Bottom Layer w10: RN4.2@6220.44,6157.8 v1(6465,6157.8) ; CN1.15@6599.17,5980.63 6600.59,5982.05 6770,5982.05 6787.24,5999.29 RN13.8@6849.56,5999.29
IO9: CN1.11 RN4.3 RN13.7 | length 784.5
  Top Layer w10: v1(6465,6126.3) 6530,6061.3 6530,5967.05 6570,5927.05 6710.03,5927.05 CN1.11@6710.99,5926.1
  Bottom Layer w10: RN4.3@6220.44,6126.3 v1(6465,6126.3) ; CN1.11@6710.99,5926.1 6760.98,5926.1 6802.68,5967.8 RN13.7@6849.56,5967.8
IO10: CN1.16 RN4.4 RN13.6 | length 803.5
  Top Layer w10: v1(6465,6094.81) 6505,6054.81 6505,5960.75 6594.17,5871.58 CN1.16@6599.17,5871.58
  Bottom Layer w10: RN4.4@6220.44,6094.81 v1(6465,6094.81) ; CN1.16@6599.17,5871.58 6599.64,5872.05 6760,5872.05 6824.25,5936.3 RN13.6@6849.56,5936.3
IO11: CN1.12 RN5.1 RN13.5 | length 902.7
  Bottom Layer w10: RN5.1@6220.44,5589.29 6352.76,5589.29 6405,5537.05 6465,5537.05 6500,5572.05 6500,5742.05 6575,5817.05 CN1.12@6710.98,5817.05 6756.81,5817.05 6844.56,5904.81 RN13.5@6849.56,5904.81
IO12: CN1.17 R2.1 RN5.2 | length 880.4
  Bottom Layer w10: RN5.2@6220.44,5557.8 6344.25,5557.8 6390,5512.05 6480,5512.05 6520,5552.05 6520,5708.35 6574.17,5762.52 CN1.17@6599.17,5762.52 6599.64,5762.05 6750,5762.05 6825,5837.05 R2.1@6855.34,5837.05
IO13: CN1.13 R1.1 RN5.3 | length 843.7
  Bottom Layer w10: RN5.3@6220.44,5526.3 6340.75,5526.3 6380,5487.05 6490,5487.05 6540,5537.05 6540,5677.05 6570.94,5707.99 CN1.13@6710.99,5707.99 6750.98,5707.99 6810.79,5767.8 R1.1@6849.56,5767.8
IO/1: H4.42 H6.41 RN15.1 U8.1 | length 737.6
  Top Layer w6: H4.42@3485,6367.05 3630.07,6221.98 3630.07,6057.89 3690.2,5997.76 U8.1@3755.86,5997.76
  Bottom Layer w10: RN15.1@6920.44,6399.29 6938.19,6417.05 7060,6417.05 H6.41@7110,6367.05
IO/2: H4.41 H6.42 RN15.2 U8.2 | length 718
  Top Layer w6: H4.41@3385,6367.05 3435,6317.05 3518.03,6317.05 3618.07,6217.01 3618.07,6052.92 3692.92,5978.07 U8.2@3755.86,5978.07
  Bottom Layer w10: RN15.2@6920.44,6367.8 7009.25,6367.8 H6.42@7010,6367.05
IO/3: H4.40 H6.39 RN15.3 U8.3 | length 674.4
  Top Layer w6: H4.40@3485,6267.05 3606.07,6145.98 3606.07,6047.95 3695.63,5958.39 U8.3@3755.86,5958.39
  Bottom Layer w10: RN15.3@6920.44,6336.3 6950.75,6336.3 6970,6317.05 7060,6317.05 H6.39@7110,6267.05
IO/4: H4.39 H6.40 RN15.4 U8.4 | length 669.5
  Top Layer w6: H4.39@3385,6267.05 3435,6217.05 3518.03,6217.05 3594.07,6141.01 3594.07,6042.98 3698.35,5938.7 U8.4@3755.86,5938.7
  Bottom Layer w10: RN15.4@6920.44,6304.81 6958.19,6267.05 H6.40@7010,6267.05
IO/5: H4.38 H6.37 RN14.1 U8.5 | length 610
  Top Layer w6: H4.38@3485,6167.05 3582.07,6069.98 3582.07,6038.01 3701.06,5919.02 U8.5@3755.86,5919.02
  Bottom Layer w10: RN14.1@6920.44,6199.29 6938.19,6217.05 7060,6217.05 H6.37@7110,6167.05
IO/6: H4.37 H6.38 RN14.2 U8.6 | length 590.4
  Top Layer w6: H4.37@3385,6167.05 3435,6117.05 3518.03,6117.05 3570.07,6065.01 3570.07,6033.03 3703.78,5899.33 U8.6@3755.86,5899.33
  Bottom Layer w10: RN14.2@6920.44,6167.8 7009.25,6167.8 H6.38@7010,6167.05
IO/7: H4.36 H6.35 RN14.3 U8.7 | length 566.7
  Top Layer w6: H4.36@3485,6067.05 3525.02,6027.02 3559.11,6027.02 3706.49,5879.65 U8.7@3755.86,5879.65
  Bottom Layer w10: RN14.3@6920.44,6136.3 6950.75,6136.3 6970,6117.05 7060,6117.05 H6.35@7110,6067.05
IO/8: H4.35 H6.36 RN14.4 U8.8 | length 561.9
  Top Layer w6: H4.35@3385,6067.05 3437.02,6015.02 3554.14,6015.02 3709.21,5859.96 U8.8@3755.86,5859.96
  Bottom Layer w10: RN14.4@6920.44,6104.81 6958.19,6067.05 H6.36@7010,6067.05
IO/11: H4.34 H6.33 RN13.1 U8.11 | length 557.3
  Top Layer w6: H4.34@3485,5967.05 3651.14,5800.91 U8.11@3755.86,5800.91
  Bottom Layer w10: RN13.1@6920.44,5999.29 6938.19,6017.05 7060,6017.05 H6.33@7110,5967.05
IO/12: H4.33 H6.34 RN13.2 U8.12 | length 537.7
  Top Layer w6: H4.33@3385,5967.05 3435,5917.05 3518.03,5917.05 3653.86,5781.22 U8.12@3755.86,5781.22
  Bottom Layer w10: RN13.2@6920.44,5967.8 7009.25,5967.8 H6.34@7010,5967.05
IO/13: H4.32 H6.31 RN13.3 U8.13 | length 532.8
  Top Layer w6: H4.32@3485,5867.05 3551.06,5867.05 3656.57,5761.54 U8.13@3755.86,5761.54
  Bottom Layer w10: RN13.3@6920.44,5936.3 6950.75,5936.3 6970,5917.05 7060,5917.05 H6.31@7110,5867.05
IO/14: H4.31 H6.32 RN13.4 U8.14 | length 527.9
  Top Layer w6: H4.31@3385,5867.05 3435,5817.05 3584.09,5817.05 3659.29,5741.85 U8.14@3755.86,5741.85
  Bottom Layer w10: RN13.4@6920.44,5904.81 6958.19,5867.05 H6.32@7010,5867.05
IO/15: H4.30 H6.29 R2.2 U8.15 | length 513.8
  Top Layer w6: H4.30@3485,5767.05 3617.12,5767.05 3662,5722.17 U8.15@3755.86,5722.17
  Bottom Layer w10: R2.2@6914.66,5837.05 6944.66,5837.05 6964.66,5817.05 7060,5817.05 H6.29@7110,5767.05
IO/16: H4.29 H6.30 R1.2 U8.16 | length 487.5
  Top Layer w6: H4.29@3385,5767.05 3435,5717.05 3650.15,5717.05 3664.72,5702.48 U8.16@3755.86,5702.48
  Bottom Layer w10: R1.2@6920.44,5767.8 7009.25,5767.8 H6.30@7010,5767.05
IO/43: H4.28 H6.27 RN12.1 U8.43 | length 865.1
  Top Layer w6: H4.28@3485,5667.05 3643,5509.05 3643,5216.93 3688.94,5170.99 U8.43@3755.86,5170.99
  Bottom Layer w10: RN12.1@6920.44,5699.29 6938.19,5717.05 7060,5717.05 H6.27@7110,5667.05
IO/44: H4.27 H6.28 RN12.2 U8.44 | length 845.5
  Top Layer w6: H4.27@3385,5667.05 3435,5617.05 3518.03,5617.05 3631,5504.08 3631,5211.96 3691.66,5151.3 U8.44@3755.86,5151.3
  Bottom Layer w10: RN12.2@6920.44,5667.8 7009.25,5667.8 H6.28@7010,5667.05
IO/45: H4.26 H6.25 RN12.3 U8.45 | length 840.6
  Top Layer w6: H4.26@3485,5567.05 3551.06,5567.05 3619,5499.11 3619,5206.99 3694.37,5131.62 U8.45@3755.86,5131.62
  Bottom Layer w10: RN12.3@6920.44,5636.3 6950.75,5636.3 6970,5617.05 7060,5617.05 H6.25@7110,5567.05
IO/46: H4.25 H6.26 RN12.4 U8.46 | length 835.7
  Top Layer w6: H4.25@3385,5567.05 3435,5517.05 3584.09,5517.05 3607,5494.14 3607,5202.02 3697.09,5111.93 U8.46@3755.86,5111.93
  Bottom Layer w10: RN12.4@6920.44,5604.81 6958.19,5567.05 H6.26@7010,5567.05
IO/47: H4.24 H6.23 RN11.1 U8.47 | length 737.5
  Top Layer w6: H4.24@3485,5467.05 3595,5357.05 3595,5197.05 3699.8,5092.25 U8.47@3755.86,5092.25
  Bottom Layer w10: RN11.1@6920.44,5499.29 6938.19,5517.05 7060,5517.05 H6.23@7110,5467.05
IO/48: H4.23 H6.24 RN11.2 U8.48 | length 717.9
  Top Layer w6: H4.23@3385,5467.05 3435,5417.05 3518.03,5417.05 3583,5352.08 3583,5192.08 3702.52,5072.56 U8.48@3755.86,5072.56
  Bottom Layer w10: RN11.2@6920.44,5467.8 7009.25,5467.8 H6.24@7010,5467.05
IO/49: H4.22 H6.21 RN11.3 U8.49 | length 674.3
  Top Layer w6: H4.22@3485,5367.05 3571,5281.05 3571,5187.11 3705.23,5052.88 U8.49@3755.86,5052.88
  Bottom Layer w10: RN11.3@6920.44,5436.3 6950.75,5436.3 6970,5417.05 7060,5417.05 H6.21@7110,5367.05
IO/50: H4.21 H6.22 RN11.4 U8.50 | length 669.4
  Top Layer w6: H4.21@3385,5367.05 3435,5317.05 3518.03,5317.05 3559,5276.08 3559,5182.14 3707.95,5033.19 U8.50@3755.86,5033.19
  Bottom Layer w10: RN11.4@6920.44,5404.81 6958.19,5367.05 H6.22@7010,5367.05
IO/53: H4.20 H6.19 RN10.1 U8.53 | length 661.4
  Top Layer w6: H4.20@3485,5267.05 3547,5205.05 3547,5177.17 3661,5063.17 3661,5003.02 3689.88,4974.14 U8.53@3755.86,4974.14
  Bottom Layer w10: RN10.1@6920.44,5299.29 6938.19,5317.05 7060,5317.05 H6.19@7110,5267.05
IO/54: H4.19 H6.20 RN10.2 U8.54 | length 641.8
  Top Layer w6: H4.19@3385,5267.05 3435,5217.05 3518.03,5217.05 3535,5200.08 3535,5172.2 3649,5058.2 3649,4998.05 3692.6,4954.45 U8.54@3755.86,4954.45
  Bottom Layer w10: RN10.2@6920.44,5267.8 7009.25,5267.8 H6.20@7010,5267.05
IO/55: H4.18 H6.17 RN10.3 U8.55 | length 620.6
  Top Layer w6: H4.18@3485,5167.05 3523.18,5167.05 3637,5053.22 3637,4993.08 3695.31,4934.77 U8.55@3755.86,4934.77
  Bottom Layer w10: RN10.3@6920.44,5236.3 6950.75,5236.3 6970,5217.05 7060,5217.05 H6.17@7110,5167.05
IO/56: H4.17 H6.18 RN10.4 U8.56 | length 615.7
  Top Layer w6: H4.17@3385,5167.05 3435,5117.05 3556.21,5117.05 3625,5048.25 3625,4988.11 3698.03,4915.08 U8.56@3755.86,4915.08
  Bottom Layer w10: RN10.4@6920.44,5204.81 6958.19,5167.05 H6.18@7010,5167.05
IO/57: H4.16 H6.15 RN9.1 U8.57 | length 559.6
  Top Layer w6: H4.16@3485,5067.05 3523,5029.05 3567.09,5029.05 3700.74,4895.4 U8.57@3755.86,4895.4
  Bottom Layer w10: RN9.1@6920.44,5099.29 6938.19,5117.05 7060,5117.05 H6.15@7110,5067.05
IO/58: H4.15 H6.16 RN9.2 U8.58 | length 540
  Top Layer w6: H4.15@3385,5067.05 3435,5017.05 3562.12,5017.05 3703.46,4875.71 U8.58@3755.86,4875.71
  Bottom Layer w10: RN9.2@6920.44,5067.8 7009.25,5067.8 H6.16@7010,5067.05
IO/59: H4.14 H6.13 RN9.3 U8.59 | length 535.1
  Top Layer w6: H4.14@3485,4967.05 3523,4929.05 3633.15,4929.05 3706.17,4856.03 U8.59@3755.86,4856.03
  Bottom Layer w10: RN9.3@6920.44,5036.3 6950.75,5036.3 6970,5017.05 7060,5017.05 H6.13@7110,4967.05
IO/60: H4.13 H6.14 RN9.4 U8.60 | length 530.2
  Top Layer w6: H4.13@3385,4967.05 3435,4917.05 3628.18,4917.05 3708.89,4836.34 U8.60@3755.86,4836.34
  Bottom Layer w10: RN9.4@6920.44,5004.81 6958.19,4967.05 H6.14@7010,4967.05
IO/61: H4.12 H6.11 RN8.1 U8.61 | length 688.9
  Top Layer w6: H4.12@3485,4867.05 3655,4697.05 3838.41,4697.05 3854.28,4712.92 U8.61@3854.28,4737.92
  Bottom Layer w10: RN8.1@6920.44,4899.29 6938.19,4917.05 7060,4917.05 H6.11@7110,4867.05
IO/62: H4.11 H6.12 RN8.2 U8.62 | length 699.3
  Top Layer w6: H4.11@3385,4867.05 3435,4817.05 3518.03,4817.05 3650.03,4685.05 3860.57,4685.05 3873.97,4698.45 U8.62@3873.97,4737.92
  Bottom Layer w10: RN8.2@6920.44,4867.8 7009.25,4867.8 H6.12@7010,4867.05
IO/63: H4.10 H6.9 RN8.3 U8.63 | length 714.2
  Top Layer w6: H4.10@3485,4767.05 3551.06,4767.05 3645.06,4673.05 3865.54,4673.05 3893.66,4701.16 U8.63@3893.66,4737.92
  Bottom Layer w10: RN8.3@6920.44,4836.3 6950.75,4836.3 6970,4817.05 7060,4817.05 H6.9@7110,4767.05
IO/64: H4.9 H6.10 RN8.4 U8.64 | length 734.2
  Top Layer w6: H4.9@3385,4767.05 3435,4717.05 3584.09,4717.05 3640.09,4661.05 3870.51,4661.05 3894.01,4684.55 3902.5,4684.55 3913.34,4695.39 U8.64@3913.34,4737.92
  Bottom Layer w10: RN8.4@6920.44,4804.81 6958.19,4767.05 H6.10@7010,4767.05
IO/65: H4.8 H6.7 RN7.1 U8.65 | length 736.8
  Top Layer w6: H4.8@3485,4667.05 3617.12,4667.05 3635.12,4649.05 3878.35,4649.05 3901.85,4672.55 3913.53,4672.55 3933.03,4692.04 U8.65@3933.03,4737.92
  Bottom Layer w10: RN7.1@6920.44,4699.29 6938.19,4717.05 7060,4717.05 H6.7@7110,4667.05
IO/66: H4.7 H6.8 RN7.2 U8.66 | length 756.6
  Top Layer w6: H4.7@3385,4667.05 3435,4617.05 3615,4617.05 3635,4637.05 3883.32,4637.05 3906.82,4660.55 3923.5,4660.55 3952.72,4689.76 U8.66@3952.72,4737.92
  Bottom Layer w10: RN7.2@6920.44,4667.8 7009.25,4667.8 H6.8@7010,4667.05
IO/67: H4.6 H6.5 RN7.3 U8.67 | length 806
  Top Layer w6: H4.6@3485,4567.05 3581.97,4567.05 3639.97,4625.05 3888.29,4625.05 3911.79,4648.55 3933.47,4648.55 3972.39,4687.47 U8.67@3972.39,4737.92
  Bottom Layer w10: RN7.3@6920.44,4636.3 6950.75,4636.3 6970,4617.05 7060,4617.05 H6.5@7110,4567.05
IO/68: H4.5 H6.6 RN7.4 U8.68 | length 855.4
  Top Layer w6: H4.5@3385,4567.05 3435,4517.05 3548.94,4517.05 3644.94,4613.05 3893.26,4613.05 3916.76,4636.55 3943.44,4636.55 3992.09,4685.19 U8.68@3992.09,4737.92
  Bottom Layer w10: RN7.4@6920.44,4604.81 6958.19,4567.05 H6.6@7010,4567.05
IO/73: H4.4 H6.3 RN6.1 U8.73 | length 959
  Top Layer w6: H4.4@3485,4467.05 3515.91,4467.05 3649.91,4601.05 3898.24,4601.05 3921.74,4624.55 3967.65,4624.55 4025.15,4682.05 4075,4682.05 4090.51,4697.55 U8.73@4090.51,4737.92
  Bottom Layer w10: RN6.1@6920.44,4499.29 6938.19,4517.05 7060,4517.05 H6.3@7110,4467.05
IO/74: H4.3 H6.4 RN6.2 U8.74 | length 1011.3
  Top Layer w6: H4.3@3385,4467.05 3435,4417.05 3518.03,4417.05 3545,4444.02 3545,4479.17 3654.88,4589.05 3903.21,4589.05 3926.71,4612.55 3972.62,4612.55 4030.12,4670.05 4079.97,4670.05 4110.19,4700.27 U8.74@4110.19,4737.92
  Bottom Layer w10: RN6.2@6920.44,4467.8 7009.25,4467.8 H6.4@7010,4467.05
IO/75: H4.2 H6.1 RN6.3 U8.75 | length 1061.3
  Top Layer w6: H4.2@3485,4367.05 3557,4439.05 3557,4474.2 3659.85,4577.05 3908.18,4577.05 3931.68,4600.55 3977.59,4600.55 4035.09,4658.05 4091,4658.05 4129.88,4696.92 U8.75@4129.88,4737.92
  Bottom Layer w10: RN6.3@6920.44,4436.3 6950.75,4436.3 6970,4417.05 7060,4417.05 H6.1@7110,4367.05
IO/76: H4.1 H6.2 RN6.4 U8.76 | length 1155.3
  Top Layer w6: H4.1@3385,4367.05 3435,4317.05 3530,4317.05 3569,4356.05 3569,4469.22 3664.82,4565.05 3913.15,4565.05 3936.65,4588.55 3982.56,4588.55 4038.06,4644.05 4097,4644.05 4149.56,4696.61 U8.76@4149.56,4737.92
  Bottom Layer w10: RN6.4@6920.44,4404.81 6958.19,4367.05 H6.2@7010,4367.05
IO/121: H3.1 H5.2 RN26.1 U8.121 | length 853
  Top Layer w6: U8.121@5114.14,4836.34 5155.71,4836.34 5175,4817.05 5175,4577.05 H3.1@5385,4367.05
  Bottom Layer w10: H5.2@9022.01,4367.05 9069.25,4319.81 RN26.1@9249.57,4319.81
IO/122: H3.2 H5.1 RN26.2 U8.122 | length 849.6
  Top Layer w6: U8.122@5114.14,4856.03 5155.64,4856.03 5187,4824.67 5187,4582.02 5351.97,4417.05 5435,4417.05 H3.2@5485,4367.05
  Bottom Layer w10: H5.1@9122.01,4367.05 9192.01,4367.05 9207.76,4351.3 RN26.2@9249.57,4351.3
IO/123: H3.3 H5.4 RN26.3 U8.123 | length 807.5
  Top Layer w6: U8.123@5114.14,4875.71 5155.43,4875.71 5199,4832.14 5199,4653.05 H3.3@5385,4467.05
  Bottom Layer w10: H5.4@9022.01,4467.05 9072.01,4417.05 9180,4417.05 9214.25,4382.8 RN26.3@9249.57,4382.8
IO/124: H3.4 H5.3 RN26.4 U8.124 | length 804.4
  Top Layer w6: U8.124@5114.14,4895.4 5155.74,4895.4 5211,4840.14 5211,4658.02 5351.97,4517.05 5435,4517.05 H3.4@5485,4467.05
  Bottom Layer w10: H5.3@9122.01,4467.05 9165,4467.05 9217.76,4414.29 RN26.4@9249.57,4414.29
IO/125: H3.5 H5.6 RN25.1 U8.125 | length 731.9
  Top Layer w6: U8.125@5114.14,4915.08 5156.06,4915.08 5223,4848.14 5223,4729.05 H3.5@5385,4567.05
  Bottom Layer w10: H5.6@9022.01,4567.05 9069.25,4519.81 RN25.1@9249.57,4519.81
IO/126: H3.6 H5.5 RN25.2 U8.126 | length 729.2
  Top Layer w6: U8.126@5114.14,4934.77 5157.03,4934.77 5235,4856.79 5235,4734.02 5351.97,4617.05 5435,4617.05 H3.6@5485,4567.05
  Bottom Layer w10: H5.5@9122.01,4567.05 9192.01,4567.05 9207.76,4551.3 RN25.2@9249.57,4551.3
IO/127: H3.7 H5.8 RN25.3 U8.127 | length 688.9
  Top Layer w6: U8.127@5114.14,4954.45 5159.97,4954.45 5247,4867.42 5247,4805.05 H3.7@5385,4667.05
  Bottom Layer w10: H5.8@9022.01,4667.05 9072.01,4617.05 9180,4617.05 9214.25,4582.8 RN25.3@9249.57,4582.8
IO/128: H3.8 H5.7 RN25.4 U8.128 | length 687.3
  Top Layer w6: U8.128@5114.14,4974.14 5162.91,4974.14 5259,4878.05 5259,4810.02 5351.97,4717.05 5435,4717.05 H3.8@5485,4667.05
  Bottom Layer w10: H5.7@9122.01,4667.05 9165,4667.05 9217.76,4614.29 RN25.4@9249.57,4614.29
IO/131: H3.9 H5.10 RN24.1 U8.131 | length 663.4
  Top Layer w6: U8.131@5114.14,5033.19 5178.86,5033.19 5311,4901.05 5311,4841.05 H3.9@5385,4767.05
  Bottom Layer w10: H5.10@9022.01,4767.05 9069.25,4719.81 RN24.1@9249.57,4719.81
IO/132: H3.10 H5.9 RN24.2 U8.132 | length 661.8
  Top Layer w6: U8.132@5114.14,5052.88 5181.8,5052.88 5323,4911.68 5323,4846.02 5351.97,4817.05 5435,4817.05 H3.10@5485,4767.05
  Bottom Layer w10: H5.9@9122.01,4767.05 9192.01,4767.05 9207.76,4751.3 RN24.2@9249.57,4751.3
IO/133: H3.11 H5.12 RN24.3 U8.133 | length 620.3
  Top Layer w6: U8.133@5114.14,5072.56 5182.63,5072.56 5385,4870.19 H3.11@5385,4867.05
  Bottom Layer w10: H5.12@9022.01,4867.05 9072.01,4817.05 9180,4817.05 9214.25,4782.8 RN24.3@9249.57,4782.8
IO/134: H3.12 H5.11 RN24.4 U8.134 | length 613.6
  Top Layer w6: U8.134@5114.14,5092.25 5185.56,5092.25 5360.76,4917.05 5435,4917.05 H3.12@5485,4867.05
  Bottom Layer w10: H5.11@9122.01,4867.05 9165,4867.05 9217.76,4814.29 RN24.4@9249.57,4814.29
IO/135: H3.13 H5.14 RN23.1 U8.135 | length 578
  Top Layer w6: U8.135@5114.14,5111.93 5191.81,5111.93 5306.69,4997.05 5355,4997.05 H3.13@5385,4967.05
  Bottom Layer w10: H5.14@9022.01,4967.05 9069.25,4919.81 RN23.1@9249.57,4919.81
IO/136: H3.14 H5.13 RN23.2 U8.136 | length 573.1
  Top Layer w6: U8.136@5114.14,5131.62 5194.75,5131.62 5309.32,5017.05 5435,5017.05 H3.14@5485,4967.05
  Bottom Layer w10: H5.13@9122.01,4967.05 9192.01,4967.05 9207.76,4951.3 RN23.2@9249.57,4951.3
IO/137: H3.15 H5.16 RN23.3 U8.137 | length 568.2
  Top Layer w6: U8.137@5114.14,5151.3 5200.75,5151.3 5250,5102.05 5350,5102.05 H3.15@5385,5067.05
  Bottom Layer w10: H5.16@9022.01,5067.05 9072.01,5017.05 9180,5017.05 9214.25,4982.8 RN23.3@9249.57,4982.8
IO/138: H3.16 H5.15 RN23.4 U8.138 | length 563.3
  Top Layer w6: U8.138@5114.14,5170.99 5206.06,5170.99 5260,5117.05 5435,5117.05 H3.16@5485,5067.05
  Bottom Layer w10: H5.15@9122.01,5067.05 9165,5067.05 9217.76,5014.29 RN23.4@9249.57,5014.29
IO/139: H3.17 H5.18 RN22.1 U8.139 | length 527.8
  Top Layer w6: U8.139@5114.14,5190.67 5361.38,5190.67 H3.17@5385,5167.05
  Bottom Layer w10: H5.18@9022.01,5167.05 9069.25,5119.81 RN22.1@9249.57,5119.81
IO/140: H3.18 H5.17 RN22.2 U8.140 | length 528.4
  Top Layer w6: U8.140@5114.14,5210.36 5315,5210.36 5321.69,5217.05 5435,5217.05 H3.18@5485,5167.05
  Bottom Layer w10: H5.17@9122.01,5167.05 9192.01,5167.05 9207.76,5151.3 RN22.2@9249.57,5151.3
IO/141: H3.19 H5.20 RN22.3 U8.141 | length 548.6
  Top Layer w6: U8.141@5114.14,5230.04 5304.49,5230.04 5341.5,5267.05 H3.19@5385,5267.05
  Bottom Layer w10: H5.20@9022.01,5267.05 9072.01,5217.05 9180,5217.05 9214.25,5182.8 RN22.3@9249.57,5182.8
IO/143: H3.20 H5.19 RN22.4 U8.143 | length 560.7
  Top Layer w6: U8.143@5114.14,5269.41 5257.36,5269.41 5305,5317.05 5435,5317.05 H3.20@5485,5267.05
  Bottom Layer w10: H5.19@9122.01,5267.05 9165,5267.05 9217.76,5214.29 RN22.4@9249.57,5214.29
IO/152: H3.21 H5.22 RN21.1 U8.144 U8.152 | length 794.1
  Top Layer w6: U8.144@5114.14,5289.1 5247.05,5289.1 5325,5367.05 ; U8.152@5114.14,5446.58 5245.47,5446.58 5325,5367.05 ; H3.21@5385,5367.05 5325,5367.05
  Bottom Layer w10: H5.22@9022.01,5367.05 9069.25,5319.81 RN21.1@9249.57,5319.81
IO/153: H3.22 H5.21 RN21.2 U8.153 | length 546
  Top Layer w6: U8.153@5114.14,5466.26 5260.79,5466.26 5310,5417.05 5435,5417.05 H3.22@5485,5367.05
  Bottom Layer w10: H5.21@9122.01,5367.05 9192.01,5367.05 9207.76,5351.3 RN21.2@9249.57,5351.3
IO/156: H3.23 H5.24 RN21.3 U8.156 | length 557.5
  Top Layer w6: U8.156@5114.14,5525.32 5256.73,5525.32 5315,5467.05 H3.23@5385,5467.05
  Bottom Layer w10: H5.24@9022.01,5467.05 9072.01,5417.05 9180,5417.05 9214.25,5382.8 RN21.3@9249.57,5382.8
IO/158: H3.24 H5.23 RN21.4 U8.158 | length 560.7
  Top Layer w6: U8.158@5114.14,5564.69 5297.36,5564.69 5345,5517.05 5435,5517.05 H3.24@5485,5467.05
  Bottom Layer w10: H5.23@9122.01,5467.05 9165,5467.05 9217.76,5414.29 RN21.4@9249.57,5414.29
IO/159: H3.25 H5.26 RN20.1 U8.159 | length 525.2
  Top Layer w6: U8.159@5114.14,5584.37 5307.68,5584.37 5325,5567.05 H3.25@5385,5567.05
  Bottom Layer w10: H5.26@9022.01,5567.05 9069.25,5519.81 RN20.1@9249.57,5519.81
IO/160: H3.26 H5.25 RN20.2 U8.160 | length 531
  Top Layer w6: U8.160@5114.14,5604.06 5310,5604.06 5322.99,5617.05 5435,5617.05 H3.26@5485,5567.05
  Bottom Layer w10: H5.25@9122.01,5567.05 9192.01,5567.05 9207.76,5551.3 RN20.2@9249.57,5551.3
IO/161: H3.27 H5.28 RN20.3 U8.161 | length 551.3
  Top Layer w6: U8.161@5114.14,5623.74 5297.05,5623.74 5340.36,5667.05 H3.27@5385,5667.05
  Bottom Layer w10: H5.28@9022.01,5667.05 9072.01,5617.05 9180,5617.05 9214.25,5582.8 RN20.3@9249.57,5582.8
IO/162: H3.28 H5.27 RN20.4 U8.162 | length 571.5
  Top Layer w6: U8.162@5114.14,5643.43 5286.38,5643.43 5360,5717.05 5435,5717.05 H3.28@5485,5667.05
  Bottom Layer w10: H5.27@9122.01,5667.05 9165,5667.05 9217.76,5614.29 RN20.4@9249.57,5614.29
